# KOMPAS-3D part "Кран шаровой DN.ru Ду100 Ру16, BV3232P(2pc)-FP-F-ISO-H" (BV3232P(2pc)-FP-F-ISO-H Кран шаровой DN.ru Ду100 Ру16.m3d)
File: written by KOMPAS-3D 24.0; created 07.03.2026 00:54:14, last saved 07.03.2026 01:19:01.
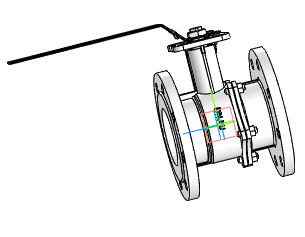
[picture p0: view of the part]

Document properties: Автор: R2D2; Полное имя файла: BV3232P(2pc)-FP-F-ISO-H Кран шаровой DN.ru Ду100 Ру16.cdw

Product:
- Part/product: Кран шаровой DN.ru Ду100 Ру16  | designation BV3232P(2pc)-FP-F-ISO-H
    Масса: 19.2
    Раздел спецификации: Прочие изделия
    Форматы листов документа: A2
    Примечание: D160-22137

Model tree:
1. Операция без истории:1

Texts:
  BV3232P(2pc)-FP-F-ISO-H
